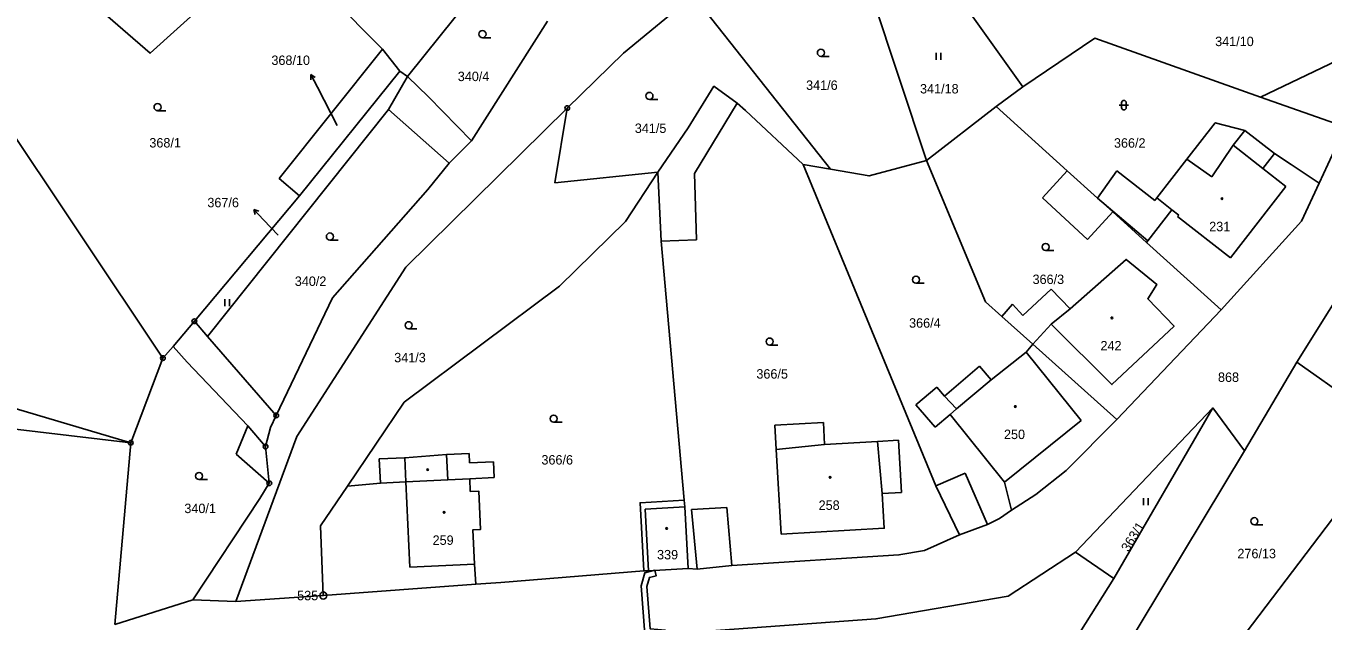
# Model space of a CAD drawing. Extents: x -745926 to -742978, y -968282 to -965689.
# Drawn here: x -744856.3 to -744718.8, y -966751.7 to -966688.6 of the extents above; entities that cross this region are included whole.
import ezdxf

# ---------------------------------------------------------------- set-up
doc = ezdxf.new("R2010")
doc.units = 0
for name, color, linetype in [('Hranice parcel', 7, 'Continuous'), ('Parcelní čísla', 7, 'Continuous'), ('Pop  PČ popisy', 7, 'Continuous'), ('Vnitřní kresba', 7, 'Continuous'), ('Věcná břemena k části', 7, 'Continuous'), ('Značky bodu BP', 7, 'Continuous'), ('Značky budov', 7, 'Continuous'), ('Značky kultur', 7, 'Continuous')]:
    doc.layers.add(name, color=color, linetype=linetype)

msp = doc.modelspace()

# ---------------------------------------------------------------- linework, layer by layer
at = {"layer": 'Hranice parcel'}
for p, q in [((-744872.94, -966677.23), (-744841.78, -966723.83)), ((-744818.49, -966691.06), (-744829.99, -966679.45)), ((-744760.83, -966702.86), (-744768.17, -966680.74)), ((-744807.32, -966683.35), (-744815.86, -966693.95)), ((-744725.41, -966696.15), (-744701.74, -966684.82)), ((-744771, -966703.8), (-744785.56, -966685.37)), ((-744757.14, -966685.91), (-744750.62, -966695.06)), ((-744816.66, -966693.39), (-744818.49, -966691.06)), ((-744816.66, -966693.39), (-744827.29, -966706.62)), ((-744815.86, -966693.95), (-744816.66, -966693.39)), ((-744815.86, -966693.95), (-744817.88, -966697.46)), ((-744753.44, -966697.13), (-744750.62, -966695.06)), ((-744817.88, -966697.46), (-744837.05, -966721.53)), ((-744811.42, -966703.17), (-744817.88, -966697.46)), ((-744760.83, -966702.86), (-744753.44, -966697.13)), ((-744773.9, -966703.3), (-744771, -966703.8)), ((-744827.29, -966706.62), (-744838.45, -966719.92)), ((-744737.5, -966711.55), (-744729.6, -966718.69)), ((-744740.63, -966730.32), (-744729.6, -966718.69)), ((-744837.05, -966721.53), (-744838.45, -966719.92)), ((-744829.77, -966729.91), (-744837.05, -966721.53)), ((-744740.63, -966730.32), (-744749.54, -966722.35)), ((-744841.78, -966723.83), (-744845.2, -966732.8)), ((-744721.55, -966724.25), (-744727.11, -966733.67)), ((-744710.9, -966731.8), (-744721.55, -966724.25)), ((-744730.45, -966729.09), (-744745.02, -966744.39)), ((-744730.45, -966729.09), (-744740.95, -966747.2)), ((-744727.11, -966733.67), (-744730.45, -966729.09)), ((-744845.2, -966732.8), (-744858.33, -966731.26)), ((-744733.65, -966761.72), (-744710.9, -966731.8)), ((-744845.2, -966732.8), (-744846.88, -966752.06)), ((-744740.95, -966747.2), (-744745.02, -966744.39)), ((-744824.78, -966749), (-744808.62, -966747.81)), ((-744740.95, -966747.2), (-744748.81, -966759.65)), ((-744846.88, -966752.06), (-744838.62, -966749.45)), ((-744838.62, -966749.45), (-744834.06, -966749.64)), ((-744834.06, -966749.64), (-744824.78, -966749))]:
    msp.add_line(p, q, dxfattribs=at)
for points in [[(-744863.06, -966670.44), (-744856.26, -966678.45), (-744854.05, -966681.52), (-744851.84, -966683.93), (-744843.15, -966691.5), (-744833.83, -966683.07), (-744829.99, -966679.45)], [(-744785.56, -966685.37), (-744792.95, -966691.5), (-744798.91, -966697.31)], [(-744811.42, -966703.17), (-744809.08, -966700.77), (-744801.02, -966688.1)], [(-744750.62, -966695.06), (-744742.99, -966689.9), (-744725.41, -966696.15)], [(-744827.29, -966706.62), (-744829.44, -966704.77), (-744818.49, -966691.06)], [(-744789.3, -966704.1), (-744786.1, -966699.4), (-744783.36, -966694.99), (-744780.9, -966696.8), (-744780, -966697.55), (-744773.9, -966703.3)], [(-744719.2, -966705.27), (-744717.35, -966701.31), (-744716.86, -966699.15), (-744725.41, -966696.15)], [(-744798.91, -966697.31), (-744816.04, -966714.19), (-744827.57, -966732.14), (-744834.06, -966749.64)], [(-744789.3, -966704.1), (-744800.23, -966705.23), (-744798.91, -966697.31)], [(-744753.44, -966697.13), (-744745.9, -966703.95), (-744742.68, -966706.86), (-744741.07, -966708.32), (-744737.5, -966711.55)], [(-744719.2, -966705.27), (-744722.15, -966703.31), (-744723.93, -966702.14), (-744727.09, -966699.68), (-744730.21, -966698.87), (-744733.21, -966702.72), (-744736.42, -966706.84), (-744734.81, -966708.1), (-744737.37, -966711.39), (-744737.5, -966711.55)], [(-744771, -966703.8), (-744766.92, -966704.51), (-744760.83, -966702.86)], [(-744760.83, -966702.86), (-744754.58, -966717.85), (-744752.85, -966719.4), (-744749.54, -966722.35)], [(-744829.77, -966729.91), (-744823.82, -966717.44), (-744813.68, -966705.96), (-744811.42, -966703.17)], [(-744822.22, -966737.39), (-744816.2, -966728.5), (-744799.72, -966716.19), (-744792.72, -966709.35), (-744789.3, -966704.1)], [(-744789.3, -966704.1), (-744788.97, -966711.44), (-744786.5, -966738.9)], [(-744773.9, -966703.3), (-744759.85, -966737.36), (-744757.34, -966742.56)], [(-744729.6, -966718.69), (-744721.07, -966709.29), (-744719.2, -966705.27)], [(-744708.45, -966706.39), (-744714.53, -966713), (-744721.55, -966724.25)], [(-744747.62, -966720.21), (-744741.17, -966726.64), (-744734.58, -966720.43), (-744737.36, -966717.53), (-744736.4, -966716.02), (-744739.66, -966713.36), (-744745.6, -966718.6), (-744747.62, -966720.21)], [(-744838.45, -966719.92), (-744840.7, -966722.6), (-744841.78, -966723.83)], [(-744749.54, -966722.35), (-744750.25, -966723.18), (-744753.98, -966726.12), (-744757.63, -966729.21), (-744758.32, -966729.8), (-744752.56, -966736.98), (-744751.8, -966739.95)], [(-744838.62, -966749.45), (-744831.5, -966738.7), (-744830.5, -966737.1), (-744830.9, -966733.2), (-744830.37, -966731.17), (-744829.77, -966729.91)], [(-744751.8, -966739.95), (-744749.23, -966738.28), (-744746.02, -966735.74), (-744740.63, -966730.32)], [(-744776.23, -966742.49), (-744765.3, -966741.87), (-744765.51, -966738.18), (-744766.01, -966732.66), (-744771.63, -966732.98), (-744776.75, -966733.51), (-744776.23, -966742.49)], [(-744808.62, -966747.81), (-744808.76, -966745.66), (-744808.93, -966742.04), (-744808.1, -966742), (-744808.3, -966737.92), (-744809.19, -966737.97), (-744809.25, -966736.61), (-744811.58, -966736.73), (-744811.72, -966734.06), (-744816.14, -966734.39), (-744816.03, -966736.96), (-744818.72, -966737.09), (-744822.22, -966737.39)], [(-744727.11, -966733.67), (-744740.35, -966755.69), (-744733.65, -966761.72)], [(-744822.22, -966737.39), (-744825.06, -966741.6), (-744824.78, -966749)], [(-744786.5, -966738.9), (-744791.19, -966739.17), (-744790.78, -966746.4)], [(-744786.09, -966746.14), (-744786.46, -966739.61), (-744786.5, -966738.9)], [(-744757.34, -966742.56), (-744754.37, -966741.46), (-744753.09, -966740.82), (-744751.8, -966739.95)], [(-744786.09, -966746.14), (-744785.13, -966746.19), (-744781.45, -966745.81), (-744763.75, -966744.69), (-744761.03, -966744.23), (-744757.34, -966742.56)], [(-744745.02, -966744.39), (-744752.16, -966749.07), (-744766.19, -966751.48), (-744786.05, -966752.91), (-744805.06, -966754.1)], [(-744808.62, -966747.81), (-744805.95, -966747.61), (-744790.78, -966746.4)], [(-744790.78, -966746.4), (-744790.3, -966746.37), (-744786.09, -966746.14)]]:
    msp.add_lwpolyline(points, dxfattribs=at)
at = {"layer": 'Pop  PČ popisy'}
for p, q in [((-744825.41, -966695.08), (-744826.09, -966693.74)), ((-744826.09, -966693.74), (-744825.64, -966694.08)), ((-744826.09, -966693.74), (-744826.09, -966694.3)), ((-744823.32, -966699.17), (-744825.41, -966695.08)), ((-744831.12, -966709.15), (-744832.16, -966708.07)), ((-744832.16, -966708.07), (-744831.63, -966708.26)), ((-744832.16, -966708.07), (-744831.99, -966708.6)), ((-744829.56, -966710.79), (-744831.12, -966709.15))]:
    msp.add_line(p, q, dxfattribs=at)
at = {"layer": 'Vnitřní kresba'}
for p, q in [((-744813.63, -966696.12), (-744815.86, -966693.95)), ((-744809.08, -966700.77), (-744813.63, -966696.12)), ((-744785.41, -966704.26), (-744780.9, -966696.8)), ((-744727.09, -966699.68), (-744728.31, -966701.26)), ((-744730.59, -966704.59), (-744728.31, -966701.26)), ((-744728.31, -966701.26), (-744725.16, -966703.72)), ((-744733.21, -966702.72), (-744730.59, -966704.59)), ((-744725.16, -966703.72), (-744723.93, -966702.14)), ((-744785.2, -966711.3), (-744785.41, -966704.26)), ((-744748.52, -966706.84), (-744745.9, -966703.95)), ((-744742.68, -966706.86), (-744740.64, -966703.97)), ((-744740.64, -966703.97), (-744736.62, -966707.1)), ((-744725.16, -966703.72), (-744722.71, -966705.62)), ((-744722.71, -966705.62), (-744728.6, -966713.18)), ((-744743.74, -966711.26), (-744748.52, -966706.84)), ((-744742.68, -966706.86), (-744737.37, -966711.39)), ((-744736.42, -966706.84), (-744736.62, -966707.1)), ((-744741.07, -966708.32), (-744743.74, -966711.26)), ((-744734.08, -966708.66), (-744734.81, -966708.1)), ((-744734.2, -966708.82), (-744734.08, -966708.66)), ((-744728.6, -966713.18), (-744734.2, -966708.82)), ((-744788.97, -966711.44), (-744785.2, -966711.3)), ((-744750.6, -966719.3), (-744747.6, -966716.52)), ((-744747.6, -966716.52), (-744745.6, -966718.6)), ((-744752.85, -966719.4), (-744751.7, -966718.11)), ((-744751.7, -966718.11), (-744750.6, -966719.3)), ((-744747.62, -966720.21), (-744749.54, -966722.35)), ((-744839.22, -966724.24), (-744840.7, -966722.6)), ((-744750.25, -966723.18), (-744744.42, -966730.44)), ((-744832.77, -966731), (-744839.22, -966724.24)), ((-744758.92, -966727.85), (-744755.19, -966724.69)), ((-744755.19, -966724.69), (-744753.98, -966726.12)), ((-744761.94, -966728.77), (-744759.73, -966726.9)), ((-744759.73, -966726.9), (-744758.92, -966727.85)), ((-744757.63, -966729.21), (-744758.92, -966727.85)), ((-744759.92, -966731.15), (-744761.94, -966728.77)), ((-744758.32, -966729.8), (-744759.92, -966731.15)), ((-744744.42, -966730.44), (-744752.56, -966736.98)), ((-744834, -966734), (-744832.77, -966731)), ((-744830.9, -966733.2), (-744832.77, -966731)), ((-744776.89, -966730.94), (-744771.76, -966730.65)), ((-744776.75, -966733.51), (-744776.89, -966730.94)), ((-744771.76, -966730.65), (-744771.63, -966732.98)), ((-744766.01, -966732.66), (-744763.78, -966732.54)), ((-744763.78, -966732.54), (-744763.47, -966738.07)), ((-744830.5, -966737.1), (-744834, -966734)), ((-744818.84, -966734.52), (-744816.14, -966734.39)), ((-744818.72, -966737.09), (-744818.84, -966734.52)), ((-744811.72, -966734.06), (-744809.31, -966733.94)), ((-744809.31, -966733.94), (-744809.26, -966734.94)), ((-744809.26, -966734.94), (-744806.74, -966734.81)), ((-744806.74, -966734.81), (-744806.65, -966736.47)), ((-744759.85, -966737.36), (-744756.74, -966736.01)), ((-744756.74, -966736.01), (-744754.37, -966741.46)), ((-744816.03, -966736.96), (-744811.58, -966736.73)), ((-744815.59, -966745.99), (-744816.03, -966736.96)), ((-744806.65, -966736.47), (-744809.25, -966736.61)), ((-744763.47, -966738.07), (-744765.51, -966738.18)), ((-744790.66, -966739.84), (-744786.46, -966739.61)), ((-744790.3, -966746.37), (-744790.66, -966739.84)), ((-744785.74, -966739.87), (-744781.98, -966739.65)), ((-744785.13, -966746.19), (-744785.74, -966739.87)), ((-744781.98, -966739.65), (-744781.45, -966745.81)), ((-744808.76, -966745.66), (-744815.59, -966745.99))]:
    msp.add_line(p, q, dxfattribs=at)
msp.add_lwpolyline([(-744861.01, -966728.18), (-744860.69, -966728.22), (-744845.2, -966732.8)], dxfattribs=at)
at = {"layer": 'Věcná břemena k části'}
msp.add_lwpolyline([(-744791.09, -966747.99), (-744790.68, -966753.1), (-744790.03, -966753.16), (-744788.55, -966753.07), (-744788.51, -966752.69), (-744790.12, -966752.54), (-744790.49, -966748.05), (-744790.21, -966747.08), (-744789.47, -966746.9), (-744789.61, -966746.33), (-744790.69, -966746.58)], close=True, dxfattribs=at)
at = {"layer": 'Značky bodu BP'}
for centre, radius in [((-744798.91, -966697.31), 0.25), ((-744798.91, -966697.31), 0.0152), ((-744838.45, -966719.92), 0.25), ((-744838.45, -966719.92), 0.0152), ((-744841.78, -966723.83), 0.25), ((-744841.78, -966723.83), 0.0152), ((-744829.77, -966729.91), 0.25), ((-744829.77, -966729.91), 0.0152), ((-744845.2, -966732.8), 0.25), ((-744845.2, -966732.8), 0.0152), ((-744830.9, -966733.2), 0.25), ((-744830.9, -966733.2), 0.0152), ((-744830.5, -966737.1), 0.25), ((-744830.5, -966737.1), 0.0152), ((-744824.78, -966749), 0.375), ((-744824.78, -966749), 0.015)]:
    msp.add_circle(centre, radius, dxfattribs=at)
at = {"layer": 'Značky budov'}
for centre in [(-744729.5, -966706.92), (-744741.17, -966719.56), (-744751.4, -966728.96), (-744813.71, -966735.65), (-744771.04, -966736.47), (-744811.97, -966740.18), (-744788.37, -966741.89)]:
    msp.add_circle(centre, 0.0875, dxfattribs=at)
at = {"layer": 'Značky kultur'}
for p, q in [((-744807.9, -966689.85), (-744807.02, -966689.85)), ((-744772.02, -966691.83), (-744771.14, -966691.83)), ((-744759.81, -966692.21), (-744759.81, -966691.46)), ((-744759.31, -966692.21), (-744759.31, -966691.46)), ((-744842.35, -966697.59), (-744841.47, -966697.59)), ((-744790.2, -966696.4), (-744789.32, -966696.4)), ((-744740.4, -966697), (-744739.4, -966697)), ((-744740.15, -966696.75), (-744740.15, -966697.25)), ((-744739.65, -966697.25), (-744739.65, -966696.75)), ((-744824.08, -966711.31), (-744823.2, -966711.31)), ((-744748.19, -966712.42), (-744747.31, -966712.42)), ((-744761.94, -966715.89), (-744761.06, -966715.89)), ((-744835.23, -966718.32), (-744835.23, -966717.57)), ((-744834.72, -966718.32), (-744834.72, -966717.57)), ((-744815.73, -966720.72), (-744814.85, -966720.72)), ((-744777.46, -966722.45), (-744776.58, -966722.45)), ((-744800.35, -966730.63), (-744799.47, -966730.63)), ((-744837.95, -966736.71), (-744837.07, -966736.71)), ((-744737.83, -966739.41), (-744737.83, -966738.66)), ((-744737.33, -966739.41), (-744737.33, -966738.66)), ((-744726.06, -966741.5), (-744725.18, -966741.5))]:
    msp.add_line(p, q, dxfattribs=at)
for centre in [(-744807.9, -966689.47), (-744772.02, -966691.45), (-744790.2, -966696.02), (-744842.35, -966697.21), (-744824.08, -966710.93), (-744748.19, -966712.04), (-744761.94, -966715.51), (-744815.73, -966720.34), (-744777.46, -966722.07), (-744800.35, -966730.25), (-744837.95, -966736.33), (-744726.06, -966741.12)]:
    msp.add_circle(centre, 0.375, dxfattribs=at)
for centre, start, end in [((-744739.9, -966696.75), 0, 180), ((-744739.9, -966697.25), 180, 359.9879)]:
    msp.add_arc(centre, 0.25, start, end, dxfattribs=at)

# ---------------------------------------------------------------- texts
at = {"layer": 'Parcelní čísla'}
for s, p in [('341/10', (-744730.22, -966690.74)), ('368/10', (-744830.28, -966692.74)), ('340/4', (-744810.52, -966694.45)), ('341/6', (-744773.59, -966695.38)), ('341/18', (-744761.51, -966695.76)), ('341/5', (-744791.75, -966699.95)), ('368/1', (-744843.22, -966701.49)), ('366/2', (-744740.95, -966701.51)), ('367/6', (-744837.07, -966707.83)), ('231', (-744730.85, -966710.37)), ('340/2', (-744827.8, -966716.17)), ('366/3', (-744749.58, -966715.97)), ('366/4', (-744762.67, -966720.6)), ('242', (-744742.38, -966723.01)), ('341/3', (-744817.26, -966724.27)), ('366/5', (-744778.86, -966726)), ('868', (-744729.92, -966726.35)), ('250', (-744752.61, -966732.41)), ('366/6', (-744801.65, -966735.11)), ('340/1', (-744839.51, -966740.26)), ('258', (-744772.26, -966739.92)), ('259', (-744813.19, -966743.63)), ('339', (-744789.39, -966745.17)), ('276/13', (-744727.86, -966745.05))]:
    msp.add_text(s, height=1, dxfattribs=at).set_placement(p)
msp.add_text('363/1', height=1, rotation=58, dxfattribs=at).set_placement((-744739.41, -966744.45))
at = {"layer": 'Značky bodu BP'}
msp.add_text('535', height=1, dxfattribs=at).set_placement((-744827.55, -966749.5))

doc.saveas('drawing.dxf')
